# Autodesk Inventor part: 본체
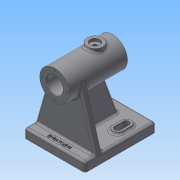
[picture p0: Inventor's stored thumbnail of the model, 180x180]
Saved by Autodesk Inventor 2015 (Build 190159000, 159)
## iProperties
Created: 2019-10
Part Number: 본체
Material: 일반
Document SubType Name: Modeling
Designer: user
Density: 1 g/cm^3
Appearance: 기본값
Author: user
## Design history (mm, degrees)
sketch "스케치1"
  geometry: C1 r 21 at (0, 0); 1 further point
  constraints: 1 centre point, 1 coincident
  dimensions: "d0" = 42 diameter of C1
extrude "돌출1" new body sketch "스케치1" stored distance "d1" = 82; taper "d2" = 0 deg
hole "구멍1" diameter "d5" = 23; stored, may be unused: countersink angle "d9" = 90 deg, drill point angle "d11" = 0 deg; dims "d3" = 10, "d4" = 10, "d6" = 6, "d7" = 4, "d8" = 2, "d10" = 20
hole "구멍2" diameter "d14" = 29; stored, may be unused: countersink angle "d18" = 90 deg, drill point angle "d20" = 0 deg; dims "d12" = 10, "d13" = 10, "d15" = 6, "d16" = 4, "d17" = 2, "d19" = 62
chamfer "모따기1" distance "d21" = 1; stored, may be unused: second distance "d22" = 2, angle "d23" = 45 deg
node "작업 평면1"
node "작업 평면2"
node "작업축1"
sketch "스케치2"
  geometry: C1 r 11 at (0, -16); 2 further points
  constraints: 1 centre point, 1 coincident
  dimensions: "d26" = 22 diameter of C1
extrude "돌출2" join sketch "스케치2" stored distance "d27" = 82; taper "d28" = 0 deg
hole "구멍3" diameter "d31" = 4.917; stored, may be unused: countersink angle "d35" = 90 deg, drill point angle "d37" = 0 deg; dims "d29" = 10, "d30" = 10, "d32" = 12, "d33" = 14, "d34" = 4, "d36" = 20.6
fillet "모깎기1" dims "d38" = 3
sketch "스케치3"
  geometry: C1 r 21 at (0, 0) reference; 1 further point
  constraints: 1 vertical alignment
  dimensions: "d39" = 18 distance of point (0, 18) C1.centre
hole "구멍4" sketch "스케치3" at (0, 18) diameter "d40" = 2.459; stored, may be unused: countersink angle "d44" = 90 deg, drill point angle "d46" = 118 deg; dims "d41" = 8, "d42" = 14, "d43" = 4, "d45" = 10
node "작업축2"
  node "작업 평면3"
  node "작업 평면4"
sketch "스케치4"
  geometry: L1 (29.4, 41)-(-29.4, 41) reference; L2 (-43, -59)-(43, -59); L3 (43, -59)-(43, 41); L4 (43, 41)-(-43, 41); L5 (-43, 41)-(-43, -59); L6 (-43, -59)-(43, 41); L7 (43, -59)-(-43, 41); 3 further points
  constraints: 12 end point, 3 midpoint, 2 parallel, 1 horizontal, 1 perpendicular, 1 point on line, 1 vertical alignment
  dimensions: "d52" = 100 distance of L2.end L3.end; "d53" = 86 distance of L2.start L2.end
extrude "돌출3" join sketch "스케치4" distance "d54" = 13; taper "d55" = 0 deg
node "작업 평면5"
fillet "모깎기2" dims "d57" = 3
fillet "모깎기3" dims "d58" = 3
sketch "스케치7"
  geometry: L1 (-27, 21)-(-27, 33); L2 (-20, 21)-(-20, 33); L3 (-34, 33)-(-34, 21); L4 (40, 59)-(-40, 59) reference; A1 r 7 centre (-27, 21) between (-34, 21) and (-20, 21); A2 r 7 centre (-27, 33) between (-20, 33) and (-34, 33); 2 further points
  constraints: 8 end point, 4 point on circle, 4 tangent, 2 centre point, 1 midpoint, 1 parallel, 1 vertical
  dimensions: "d73" = 14 distance between parallel lines of L3 L2; "d74" = 12 distance of L1.start L1.end; "d76" = 26 distance from line of L1.end L4; "d77" = 27 horizontal distance of point (-27, 27) point (0, 0)
extrude "돌출4" join sketch "스케치7" distance "d78" = 3; taper "d79" = 0 deg
sketch "스케치8"
  geometry: L1 (-27, 21)-(-27, 33); L2 (-22.5, 21)-(-22.5, 33); L3 (-31.5, 33)-(-31.5, 21); L4 (40, 59)-(-40, 59) reference; A1 r 4.5 centre (-27, 21) between (-31.5, 21) and (-22.5, 21); A2 r 4.5 centre (-27, 33) between (-22.5, 33) and (-31.5, 33); 2 further points
  constraints: 8 end point, 4 point on circle, 4 tangent, 2 centre point, 1 midpoint, 1 parallel, 1 vertical
  dimensions: "d80" = 9 distance between parallel lines of L3 L2; "d81" = 12 distance of L1.start L1.end; "d83" = 26 distance from line of L4 L1.end; "d84" = 27 horizontal distance of point (0, 0) point (-27, 27)
extrude "돌출5" cut sketch "스케치8" stored distance "d85" = 3; taper "d86" = 0 deg
node "작업 평면6"
sketch "스케치9"
  geometry: L1 (-40, -73)-(40, -73) reference; L2 (43, -76)-(43, -86) reference; L3 (43, -86)-(-43, -86) reference; L4 (-43, -86)-(-43, -76) reference; L5 (42.889, -75.19)-(20.22, 5.669); L6 (-42.889, -75.19)-(-20.22, 5.669); C1 r 11.5 at (0, 0) reference; A1 r 3 centre (-40, -76) between (-40, -73) and (-43, -76) reference; A2 r 3 centre (40, -76) between (43, -76) and (40, -73) reference; A3 r 21 centre (0, 0) between (20.22, 5.669) and (-20.22, 5.669) reference; 1 further point
  constraints: 4 end point, 4 point on circle, 4 tangent
extrude "돌출6" join sketch "스케치9" distance "d89" = 10; taper "d90" = 0 deg
sketch "스케치10"
  geometry: L1 (20, -18.459)-(20, -23) reference; L2 (20, -23)-(24, -23) reference; L3 (24, -23)-(24, -27) reference; L4 (21, -30)-(21, -41) reference; L5 (21, -41)-(19.23, -41) reference; L6 (19.23, -41)-(19.23, -31) reference; L7 (19.23, -31)-(18, -30.261) reference; L8 (18, -30.261)-(16.77, -31) reference; L9 (16.77, -31)-(16.77, -41) reference; L10 (16.77, -41)-(15.5, -41) reference; L11 (15.5, -41)-(14.5, -40) reference; L12 (14.5, -40)-(14.5, -18.459) reference; L13 (14.5, -18.459)-(20, -18.459) reference; L14 (11.5, 40)-(12.5, 41) reference; L15 (12.5, 41)-(16.77, 41) reference; L16 (16.77, 41)-(16.77, 31) reference; L17 (16.77, 31)-(18, 30.261) reference; L18 (18, 30.261)-(19.23, 31) reference; L19 (19.23, 31)-(19.23, 41) reference; L20 (19.23, 41)-(21, 41) reference; L21 (21, 41)-(21, -2) reference; L22 (24, -5)-(24, -9) reference; L23 (24, -9)-(20, -9) reference; L24 (20, -9)-(20, -13.542) reference; L25 (20, -13.542)-(14.5, -13.542) reference; L26 (14.5, -13.542)-(14.5, 21) reference; L27 (14.5, 21)-(11.5, 21) reference; L28 (11.5, 21)-(11.5, 40) reference; L29 (-76, -59)-(-86, -59) reference; L30 (-86, -59)-(-86, 41) reference; L31 (-86, 41)-(-76, 41) reference; L32 (-73, 38)-(-73, 26) reference; L33 (-73, 26)-(-21, 26) reference; L34 (-21, 26)-(-21, 41) reference; L35 (-21, 41)-(-19.23, 41) reference; L36 (-19.23, 41)-(-19.23, 31) reference; L37 (-19.23, 31)-(-18, 30.261) reference; L38 (-18, 30.261)-(-16.77, 31) reference; L39 (-16.77, 31)-(-16.77, 41) reference; L40 (-16.77, 41)-(-12.5, 41) reference; L41 (-12.5, 41)-(-11.5, 40) reference; L42 (-11.5, 40)-(-11.5, 21) reference; L43 (-11.5, 21)-(-14.5, 21) reference; L44 (-14.5, 21)-(-14.5, -40) reference; L45 (-14.5, -40)-(-15.5, -41) reference; L46 (-15.5, -41)-(-16.77, -41) reference; L47 (-16.77, -41)-(-16.77, -31) reference; L48 (-16.77, -31)-(-18, -30.261) reference; L49 (-18, -30.261)-(-19.23, -31) reference; L50 (-19.23, -31)-(-19.23, -41) reference; L51 (-19.23, -41)-(-21, -41) reference; L52 (-21, -41)-(-21, 16) reference; L53 (-21, 16)-(-73, 16) reference; L54 (-73, 16)-(-73, -56) reference; L55 (-21, -25.074)-(-73, -44); A1 r 3 centre (-76, -56) between (-76, -59) and (-73, -56) reference; A2 r 3 centre (-76, 38) between (-73, 38) and (-76, 41) reference; 1 further point
  constraints: 2 end point, 2 point on line, 2 other
  dimensions: "d91" = 15 distance from line of L29 L55.end; "d92" = 70 deg angle of L54 L55
feature "리브3" sketch "스케치10" dims "d93" = 1, "d94" = 10, "d95" = 0, "d96" = 0, "d97" = 1, "d98" = 1
fillet "모깎기5" dims "d99" = 3
fillet "모깎기6" dims "d100" = 3
fillet "모깎기7" dims "d101" = 3
fillet "모깎기8" dims "d102" = 3
node "작업 평면7"
sketch "스케치11"
  geometry: L1 (-40, -41)-(40, -41) reference; L2 (-43, 56)-(-43, -38) reference; 2 further points
  constraints: 1 other
  dimensions: "d104" = 43 distance from line of point (0, -34) L2; "d105" = 7 distance from line of L1 point (0, -34)
feature "엠보싱1" sketch "스케치11" dims "d0" = 42, "d106" = 0.5, "d107" = 0
node "솔리드1"
pattern_circular "원형 패턴1" dims angle "d48" = 360 deg
mirror "대칭1"
mirror "대칭2"
mirror "대칭3"
node "절단 모서리 투영3"
node "절단 모서리 투영4"
other parameters: "d24" = -25, "d25" = 24, "d50" = 0, "d51" = -86, "d56" = -15, "d88" = -15
